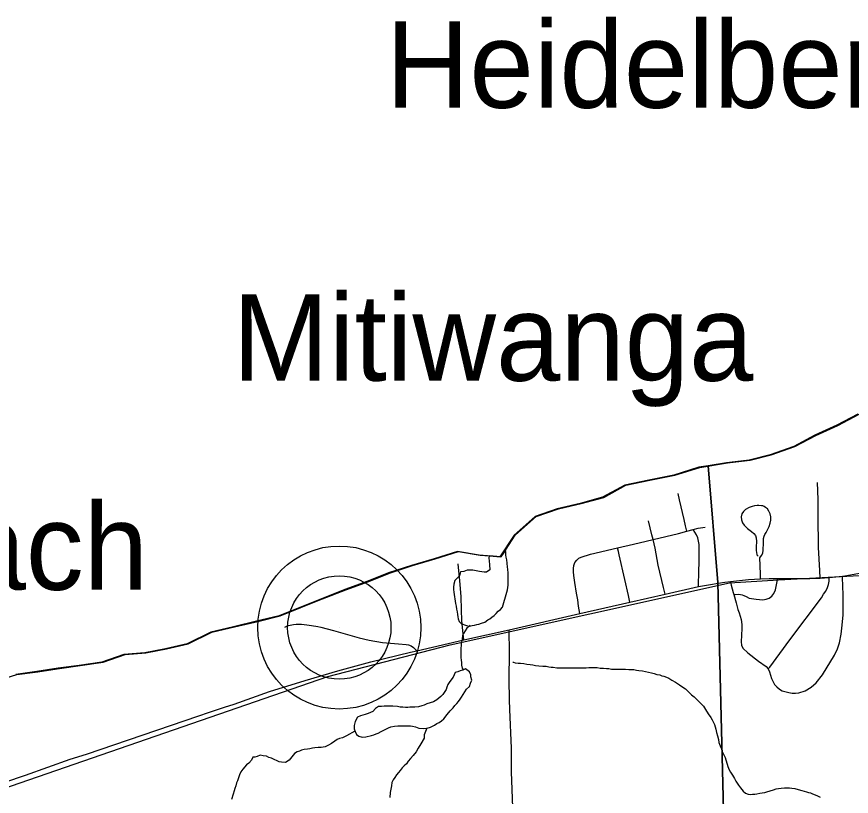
# Model space of a CAD drawing. Extents: x 0 to 34, y 0 to 22.
# Drawn here: x 7.68 to 8.441, y 18.367 to 19.079 of the extents above; entities that cross this region are included whole.
import ezdxf

# ---------------------------------------------------------------- set-up
doc = ezdxf.new("R2010")
doc.units = 0
for name, color, linetype in [('GM_X_Corporation', 7, 'Continuous'), ('GM_X_Major_Lake', 7, 'Continuous'), ('GM_X_Major_River', 7, 'Continuous'), ('GM_X_Minor_Lake', 7, 'Continuous'), ('GM_X_Minor_River', 7, 'Continuous'), ('GM_X_Rail_Line', 7, 'Continuous'), ('GM_X_Township_Road', 7, 'Continuous'), ('GM_X_Unincorporated', 7, 'Continuous'), ('GM_X_Unincorporated_Location', 7, 'Continuous'), ('GM_X_Unincorporated_Text', 7, 'Continuous'), ('GM_X_US_Route', 7, 'Continuous')]:
    doc.layers.add(name, color=color, linetype=linetype)

msp = doc.modelspace()

# ---------------------------------------------------------------- linework, layer by layer
at = {"layer": 'GM_X_Corporation'}
for points in [[(8.44753, 18.71594), (8.42818, 18.70569), (8.40806, 18.69657), (8.38909, 18.68631), (8.36745, 18.67871), (8.3481, 18.67378), (8.3276, 18.6715), (8.31086, 18.66875), (8.30218, 18.66732), (8.2794, 18.6601), (8.25663, 18.65554), (8.23461, 18.65099), (8.2145, 18.63997), (8.19401, 18.63427), (8.17313, 18.62933), (8.15302, 18.6225), (8.13366, 18.60541), (8.12075, 18.58565), (8.10178, 18.58717), (8.08205, 18.59059), (8.06079, 18.58375), (8.03992, 18.57767), (8.01905, 18.57084), (8.00007, 18.56324), (7.97919, 18.55564), (7.95794, 18.54728), (7.93821, 18.53931), (7.91923, 18.53171), (7.89873, 18.52677), (7.87748, 18.52183), (7.85699, 18.5169), (7.83535, 18.50626), (7.81562, 18.5017), (7.79664, 18.4979), (7.77766, 18.49639), (7.75755, 18.48954), (7.73668, 18.48651), (7.7177, 18.48385), (7.69796, 18.48081), (7.67899, 18.47815)], [(8.44753, 18.71594), (8.42818, 18.70569), (8.40806, 18.69657), (8.38909, 18.68631), (8.36745, 18.67871), (8.3481, 18.67378), (8.3276, 18.6715), (8.31086, 18.66875), (8.31964, 18.56207), (8.34448, 17.55856)], [(8.34448, 17.55856), (8.31964, 18.56207), (8.31086, 18.66875), (8.30218, 18.66732), (8.2794, 18.6601), (8.25663, 18.65554), (8.23461, 18.65099), (8.2145, 18.63997), (8.19401, 18.63427), (8.17313, 18.62933), (8.15302, 18.6225), (8.13366, 18.60541), (8.12075, 18.58565), (8.10178, 18.58717), (8.08205, 18.59059), (8.06079, 18.58375), (8.03992, 18.57767), (8.01905, 18.57084), (8.00007, 18.56324), (7.97919, 18.55564), (7.95794, 18.54728), (7.93821, 18.53931), (7.91923, 18.53171), (7.89873, 18.52677), (7.87748, 18.52183), (7.85699, 18.5169), (7.83535, 18.50626), (7.81562, 18.5017), (7.79664, 18.4979), (7.77766, 18.49639), (7.75755, 18.48954), (7.73668, 18.48651), (7.7177, 18.48385), (7.69796, 18.48081), (7.67899, 18.47815)]]:
    msp.add_lwpolyline(points, dxfattribs=at)
at = {"layer": 'GM_X_Major_Lake'}
for points in [[(8.12573, 18.5917), (8.13463, 18.60532), (8.15398, 18.62241), (8.1741, 18.62925), (8.19497, 18.63419), (8.21547, 18.63988), (8.23558, 18.6509), (8.2576, 18.65546), (8.28037, 18.66002), (8.30314, 18.66723), (8.32857, 18.67141), (8.34906, 18.67369), (8.36842, 18.67863), (8.39005, 18.68623), (8.40903, 18.69648), (8.42914, 18.7056), (8.4485, 18.71585)], [(7.66022, 18.47198), (7.67995, 18.47806), (7.69893, 18.48072), (7.71867, 18.48376), (7.73764, 18.48642), (7.75851, 18.48946), (7.77863, 18.4963), (7.79761, 18.49782), (7.81658, 18.50161), (7.83632, 18.50617), (7.85795, 18.51681), (7.87845, 18.52175), (7.8997, 18.52668), (7.9202, 18.53162), (7.93917, 18.53922), (7.95891, 18.5472), (7.98016, 18.55555), (8.00103, 18.56315), (8.02001, 18.57075), (8.04089, 18.57759), (8.06176, 18.58366), (8.08301, 18.5905), (8.10275, 18.58708), (8.11081, 18.58644)], [(8.11081, 18.58644), (8.11061, 18.58425), (8.11097, 18.58196), (8.11131, 18.57815), (8.11165, 18.57359), (8.10859, 18.57171), (8.10631, 18.57173), (8.10213, 18.57215), (8.09909, 18.57294), (8.09606, 18.57335), (8.0934, 18.57338), (8.09073, 18.5734), (8.08768, 18.57229), (8.08464, 18.57194), (8.08384, 18.56814), (8.07961, 18.564), (8.07882, 18.56059), (8.07841, 18.55793), (8.07839, 18.55564), (8.07874, 18.55336), (8.08016, 18.54308), (8.0809, 18.54041), (8.08125, 18.53774), (8.08161, 18.53546), (8.08196, 18.53279), (8.08232, 18.53088), (8.08268, 18.52898), (8.08342, 18.52669), (8.0853, 18.52477), (8.08833, 18.5236), (8.09022, 18.52282), (8.09288, 18.52242), (8.09555, 18.52277), (8.09745, 18.52314), (8.09974, 18.52388), (8.10164, 18.52424), (8.10393, 18.52498), (8.10699, 18.52609), (8.10967, 18.52796), (8.11158, 18.52909), (8.11349, 18.53059), (8.11541, 18.53209), (8.11733, 18.53398), (8.11925, 18.53586), (8.12117, 18.53736), (8.12309, 18.53963), (8.12703, 18.55328), (8.12781, 18.55556), (8.12824, 18.55974), (8.1283, 18.56582), (8.12835, 18.57077), (8.128, 18.57419), (8.12764, 18.5761), (8.1273, 18.57991), (8.12695, 18.58295), (8.12659, 18.58523), (8.12623, 18.58714), (8.12625, 18.58942), (8.12573, 18.5917)], [(8.11081, 18.58644), (8.12172, 18.58556), (8.12573, 18.5917)]]:
    msp.add_lwpolyline(points, dxfattribs=at)
at = {"layer": 'GM_X_Major_River'}
for points in [[(8.11081, 18.58644), (8.11061, 18.58425), (8.11097, 18.58196), (8.11131, 18.57815), (8.11165, 18.57359), (8.10859, 18.57171), (8.10631, 18.57173), (8.10213, 18.57215), (8.09909, 18.57294), (8.09606, 18.57335), (8.0934, 18.57338), (8.09073, 18.5734), (8.08768, 18.57229), (8.08464, 18.57194), (8.08384, 18.56814), (8.07961, 18.564), (8.07882, 18.56059), (8.07841, 18.55793), (8.07839, 18.55564), (8.07874, 18.55336), (8.08016, 18.54308), (8.0809, 18.54041), (8.08125, 18.53774), (8.08161, 18.53546), (8.08196, 18.53279), (8.08232, 18.53088), (8.08268, 18.52898), (8.08342, 18.52669), (8.0853, 18.52477), (8.08833, 18.5236), (8.09022, 18.52282), (8.09288, 18.52242), (8.09555, 18.52277), (8.09745, 18.52314), (8.09974, 18.52388), (8.10164, 18.52424), (8.10393, 18.52498), (8.10699, 18.52609), (8.10967, 18.52796), (8.11158, 18.52909), (8.11349, 18.53059), (8.11541, 18.53209), (8.11733, 18.53398), (8.11925, 18.53586), (8.12117, 18.53736), (8.12309, 18.53963), (8.12703, 18.55328), (8.12781, 18.55556), (8.12824, 18.55974), (8.1283, 18.56582), (8.12835, 18.57077), (8.128, 18.57419), (8.12764, 18.5761), (8.1273, 18.57991), (8.12695, 18.58295), (8.12659, 18.58523), (8.12623, 18.58714), (8.12625, 18.58942), (8.12573, 18.5917)], [(8.12573, 18.5917), (8.12172, 18.58556), (8.11081, 18.58644)]]:
    msp.add_lwpolyline(points, dxfattribs=at)
at = {"layer": 'GM_X_Minor_Lake'}
for points in [[(8.08942, 18.48326), (8.08677, 18.48216), (8.08448, 18.48142), (8.0822, 18.48068), (8.07991, 18.47994), (8.07796, 18.47578), (8.07604, 18.47313), (8.07449, 18.47087), (8.07333, 18.46897), (8.07217, 18.4667), (8.07177, 18.46442), (8.07061, 18.46253), (8.06868, 18.45989), (8.06676, 18.45801), (8.06331, 18.455), (8.06025, 18.45312), (8.0572, 18.45239), (8.05414, 18.45128), (8.05147, 18.45016), (8.04956, 18.44942), (8.04651, 18.44869), (8.04309, 18.44834), (8.04043, 18.44837), (8.03853, 18.44838), (8.03662, 18.44802), (8.03472, 18.44804), (8.03206, 18.44845), (8.02978, 18.44847), (8.02713, 18.44887), (8.02295, 18.44929), (8.02029, 18.44931), (8.01839, 18.44933), (8.01496, 18.44937), (8.01268, 18.44901), (8.01002, 18.44903), (8.00734, 18.44716), (8.00465, 18.44452), (8.00274, 18.4434), (8.00045, 18.44266), (7.99778, 18.44154), (7.99358, 18.44044), (7.99091, 18.43932), (7.98859, 18.43516), (7.98779, 18.43175), (7.98776, 18.4287), (7.98849, 18.42603)], [(8.08942, 18.48326), (8.08677, 18.48216), (8.08448, 18.48142), (8.0822, 18.48068), (8.07991, 18.47994), (8.07796, 18.47578), (8.07604, 18.47313), (8.07449, 18.47087), (8.07333, 18.46897), (8.07217, 18.4667), (8.07177, 18.46442), (8.07061, 18.46253), (8.06868, 18.45989), (8.06676, 18.45801), (8.06331, 18.455), (8.06025, 18.45312), (8.0572, 18.45239), (8.05414, 18.45128), (8.05147, 18.45016), (8.04956, 18.44942), (8.04651, 18.44869), (8.04309, 18.44834), (8.04043, 18.44837), (8.03853, 18.44838), (8.03662, 18.44802), (8.03472, 18.44804), (8.03206, 18.44845), (8.02978, 18.44847), (8.02713, 18.44887), (8.02295, 18.44929), (8.02029, 18.44931), (8.01839, 18.44933), (8.01496, 18.44937), (8.01268, 18.44901), (8.01002, 18.44903), (8.00734, 18.44716), (8.00465, 18.44452), (8.00274, 18.4434), (8.00045, 18.44266), (7.99778, 18.44154), (7.99358, 18.44044), (7.99091, 18.43932), (7.98859, 18.43516), (7.98779, 18.43175), (7.98776, 18.4287), (7.98849, 18.42603), (7.98999, 18.42336), (7.99187, 18.42182), (7.99491, 18.42103), (7.99833, 18.42138), (8.00367, 18.42247), (8.00558, 18.42321), (8.00786, 18.42395), (8.00977, 18.42469), (8.01245, 18.42619), (8.01589, 18.42806), (8.01895, 18.42955), (8.02124, 18.43029), (8.02467, 18.43102), (8.02771, 18.43137), (8.03037, 18.43135), (8.03265, 18.43132), (8.03607, 18.43129), (8.03911, 18.43126), (8.04101, 18.43086), (8.04367, 18.43046), (8.0467, 18.42929), (8.05088, 18.42887), (8.0543, 18.42922), (8.05735, 18.42995), (8.05926, 18.43107), (8.06117, 18.43182), (8.06309, 18.43332), (8.06538, 18.43444), (8.0673, 18.43594), (8.0696, 18.43782), (8.07267, 18.4416), (8.07537, 18.44499), (8.07806, 18.44763), (8.0796, 18.4499), (8.08152, 18.45178), (8.08306, 18.45367), (8.0846, 18.45556), (8.08576, 18.45745), (8.0904, 18.46463), (8.09309, 18.46727), (8.09388, 18.4703), (8.09504, 18.47295), (8.09431, 18.476), (8.09433, 18.4779), (8.09284, 18.48058), (8.08942, 18.48326)], [(7.98849, 18.42603), (7.98999, 18.42336), (7.99187, 18.42182), (7.99491, 18.42103), (7.99833, 18.42138), (8.00367, 18.42247), (8.00558, 18.42321), (8.00786, 18.42395), (8.00977, 18.42469), (8.01245, 18.42619), (8.01589, 18.42806), (8.01895, 18.42955), (8.02124, 18.43029), (8.02467, 18.43102), (8.02771, 18.43137), (8.03037, 18.43135), (8.03265, 18.43132), (8.03607, 18.43129), (8.03911, 18.43126), (8.04101, 18.43086), (8.04367, 18.43046), (8.0467, 18.42929), (8.05088, 18.42887), (8.0543, 18.42922), (8.05735, 18.42995), (8.05926, 18.43107), (8.06117, 18.43182), (8.06309, 18.43332), (8.06538, 18.43444), (8.0673, 18.43594), (8.0696, 18.43782), (8.07267, 18.4416), (8.07537, 18.44499), (8.07806, 18.44763), (8.0796, 18.4499), (8.08152, 18.45178), (8.08306, 18.45367), (8.0846, 18.45556), (8.08576, 18.45745), (8.0904, 18.46463), (8.09309, 18.46727), (8.09388, 18.4703), (8.09504, 18.47295), (8.09431, 18.476), (8.09433, 18.4779), (8.09284, 18.48058), (8.08942, 18.48326)]]:
    msp.add_lwpolyline(points, dxfattribs=at)
at = {"layer": 'GM_X_Minor_River'}
for points in [[(8.09364, 18.52279), (8.09058, 18.52054), (8.08749, 18.51562), (8.08671, 18.51373), (8.0863, 18.51031), (8.0855, 18.50689), (8.08548, 18.50499), (8.08507, 18.50195), (8.08505, 18.50005), (8.08503, 18.49815), (8.08499, 18.49359), (8.08535, 18.4913), (8.0857, 18.48902), (8.08568, 18.48673), (8.08641, 18.48406), (8.08719, 18.48233)], [(8.13247, 18.48934), (8.13323, 18.48933), (8.13475, 18.48893), (8.1374, 18.48853), (8.13968, 18.48851), (8.14272, 18.4881), (8.14538, 18.48769), (8.14842, 18.48728), (8.15069, 18.48688), (8.15335, 18.48648), (8.15639, 18.48607), (8.15981, 18.48565), (8.16285, 18.48563), (8.1655, 18.48522), (8.1674, 18.48482), (8.1693, 18.48481), (8.17272, 18.48439), (8.17462, 18.48438), (8.1769, 18.48435), (8.1788, 18.48434), (8.18071, 18.48432), (8.1826, 18.4843), (8.18451, 18.48428), (8.18679, 18.48426), (8.19477, 18.48418), (8.19705, 18.48416), (8.19933, 18.48414), (8.202, 18.4845), (8.20466, 18.48447), (8.20694, 18.48445), (8.2096, 18.48442), (8.21226, 18.48402), (8.2153, 18.48399), (8.21796, 18.48359), (8.22024, 18.48356), (8.22251, 18.48316), (8.22442, 18.48314), (8.2267, 18.48312), (8.2286, 18.4831), (8.2305, 18.48309), (8.23316, 18.48306), (8.23544, 18.48304), (8.23848, 18.48263), (8.24038, 18.48261), (8.24304, 18.48259), (8.24532, 18.48219), (8.24759, 18.48179), (8.25101, 18.48137), (8.25367, 18.48097), (8.25632, 18.48018), (8.25898, 18.47977), (8.26163, 18.47899), (8.26391, 18.47821), (8.26656, 18.4778), (8.26846, 18.47702), (8.27035, 18.47663), (8.27263, 18.47584), (8.2749, 18.47468), (8.27754, 18.47313), (8.28095, 18.4712), (8.28472, 18.46888), (8.28774, 18.46657), (8.29001, 18.46503), (8.29566, 18.45965), (8.29792, 18.45773), (8.2998, 18.45581), (8.30168, 18.45427), (8.30357, 18.45235), (8.30658, 18.44928), (8.30845, 18.44622), (8.31069, 18.4424), (8.31332, 18.43895), (8.31443, 18.43666), (8.31555, 18.43436), (8.31667, 18.43245), (8.31777, 18.42826), (8.3185, 18.42521), (8.31923, 18.42216), (8.32034, 18.41872), (8.32069, 18.41606), (8.3218, 18.41301), (8.32291, 18.41033), (8.32365, 18.40766), (8.32477, 18.40537), (8.32625, 18.40231), (8.32699, 18.40041), (8.3281, 18.39621), (8.32884, 18.3943), (8.32995, 18.39125), (8.33106, 18.38896), (8.33294, 18.38628), (8.33481, 18.38322), (8.33592, 18.38092), (8.33742, 18.37901), (8.33855, 18.37709), (8.34042, 18.3748), (8.34267, 18.37173), (8.34494, 18.36981), (8.34721, 18.36903), (8.34949, 18.36863), (8.35139, 18.36899)], [(7.98835, 18.42655), (7.98085, 18.4223), (7.97703, 18.42044), (7.97436, 18.4197), (7.97208, 18.41896), (7.97016, 18.41746), (7.96709, 18.41521), (7.96442, 18.41371), (7.96136, 18.41222), (7.95755, 18.41149), (7.95489, 18.41152), (7.95185, 18.41116), (7.94956, 18.41081), (7.94728, 18.41045), (7.94499, 18.41009), (7.94195, 18.40974), (7.93966, 18.409), (7.93775, 18.40826), (7.93584, 18.40751), (7.93316, 18.40602), (7.92854, 18.39998), (7.9251, 18.39773), (7.9213, 18.39814), (7.9194, 18.39854), (7.91751, 18.39932), (7.91486, 18.40048), (7.91221, 18.40165), (7.90994, 18.40243), (7.90767, 18.40359), (7.90463, 18.404), (7.90197, 18.40441), (7.8993, 18.40329), (7.89701, 18.40256), (7.89511, 18.40257), (7.89394, 18.39992), (7.89163, 18.39728), (7.88934, 18.39578), (7.88625, 18.39163), (7.88433, 18.38936), (7.88316, 18.38671), (7.88121, 18.38102), (7.88042, 18.37913), (7.87964, 18.37648), (7.87885, 18.3742), (7.87807, 18.37193), (7.87728, 18.36889), (7.87571, 18.36396)], [(8.05406, 18.42919), (8.05158, 18.42316), (8.05155, 18.42012), (8.04845, 18.41482), (8.04613, 18.41104), (8.0442, 18.40763), (8.0415, 18.40424), (8.0392, 18.40159), (8.03689, 18.39895), (8.03535, 18.39669), (8.03342, 18.39481), (8.0315, 18.39292), (8.02958, 18.39066), (8.02804, 18.38877), (8.0265, 18.3865), (8.02495, 18.38423), (8.02341, 18.38197), (8.02225, 18.3797), (8.02184, 18.37666), (8.02104, 18.37362), (8.02063, 18.37058), (8.02021, 18.36602)], [(8.35139, 18.36899), (8.35329, 18.36897), (8.3552, 18.36933), (8.35786, 18.36969), (8.36015, 18.37005), (8.36243, 18.37041), (8.36434, 18.37115), (8.36739, 18.37188), (8.37044, 18.37299), (8.37273, 18.37373), (8.37502, 18.37409), (8.3773, 18.37445), (8.38035, 18.3748), (8.38263, 18.37478), (8.38491, 18.37476), (8.38718, 18.37436), (8.38984, 18.37395), (8.39288, 18.37316), (8.39629, 18.37237), (8.39856, 18.37159), (8.40046, 18.37119), (8.40235, 18.37041), (8.40425, 18.37001), (8.40614, 18.36923), (8.40842, 18.36845), (8.41069, 18.36729), (8.41296, 18.36613)]]:
    msp.add_lwpolyline(points, dxfattribs=at)
at = {"layer": 'GM_X_Rail_Line'}
msp.add_lwpolyline([(6.87885, 18.29227), (7.10148, 18.25871), (7.18271, 18.24997), (7.28141, 18.25347), (7.4098, 18.28492), (7.96356, 18.47627), (8.07536, 18.5051), (8.3304, 18.56189), (8.37494, 18.56451), (8.45443, 18.56888), (8.5243, 18.58723), (8.9, 18.69387)], dxfattribs=at)
at = {"layer": 'GM_X_Township_Road'}
msp.add_line((8.29147, 18.60904), (8.29716, 18.61054), dxfattribs=at)
for points in [[(8.41302, 18.56615), (8.41265, 18.57309), (8.41152, 18.594), (8.41105, 18.62299), (8.41107, 18.63801), (8.41048, 18.65345)], [(8.29147, 18.60904), (8.29011, 18.61395), (8.28877, 18.61954), (8.28458, 18.63768), (8.28342, 18.64341)], [(8.35781, 18.58474), (8.3594, 18.58673), (8.36061, 18.58884), (8.36104, 18.59162), (8.3613, 18.59824), (8.36143, 18.60232), (8.36191, 18.60459), (8.3625, 18.60603), (8.36369, 18.60784), (8.36475, 18.60954), (8.36638, 18.61338), (8.36736, 18.61618), (8.36792, 18.61906), (8.36797, 18.62197), (8.36745, 18.62479), (8.36626, 18.62733), (8.3649, 18.62938), (8.36309, 18.63077), (8.36189, 18.63158), (8.36061, 18.63201), (8.35933, 18.63228), (8.3569, 18.6323), (8.35564, 18.6323), (8.35298, 18.63201), (8.35097, 18.63158), (8.34811, 18.63063), (8.3449, 18.6289), (8.34292, 18.62703), (8.34167, 18.62492), (8.34104, 18.62202), (8.34133, 18.61929), (8.34217, 18.61653), (8.34355, 18.61452), (8.34684, 18.61134), (8.35023, 18.6088), (8.35244, 18.60699), (8.354, 18.60519), (8.35464, 18.60289), (8.35492, 18.59972), (8.35475, 18.5947), (8.35457, 18.59237), (8.35457, 18.59099), (8.3548, 18.58972), (8.35536, 18.58745), (8.35633, 18.58627)], [(8.26059, 18.6013), (8.25936, 18.60562), (8.25624, 18.61852)], [(8.26059, 18.6013), (8.28379, 18.60689), (8.29147, 18.60904)], [(8.29716, 18.61054), (8.30176, 18.61161), (8.30793, 18.61256)], [(8.30194, 18.55852), (8.30203, 18.56246), (8.30219, 18.56904), (8.30219, 18.5719), (8.30263, 18.58134), (8.3027, 18.59074), (8.30273, 18.59381), (8.30253, 18.59685), (8.30207, 18.59984), (8.30127, 18.60279), (8.30009, 18.60564), (8.29876, 18.60825), (8.29716, 18.61054)], [(8.22796, 18.59378), (8.24273, 18.59728), (8.25427, 18.59977), (8.26059, 18.6013)], [(8.27155, 18.5516), (8.27013, 18.55763), (8.2653, 18.57805), (8.26231, 18.59335), (8.26059, 18.6013)], [(8.19274, 18.58445), (8.19481, 18.58533), (8.20328, 18.58792), (8.22796, 18.59378)], [(8.23941, 18.54425), (8.23807, 18.55038), (8.23489, 18.5649), (8.2296, 18.58728), (8.22883, 18.59033), (8.22796, 18.59378)], [(8.08774, 18.50968), (8.08693, 18.51818), (8.08604, 18.52754), (8.08559, 18.53705), (8.08523, 18.54946), (8.08422, 18.5636), (8.08277, 18.57907)], [(8.1936, 18.53378), (8.19261, 18.5405), (8.19173, 18.54642), (8.19066, 18.55244), (8.18913, 18.5621), (8.18815, 18.56863), (8.18792, 18.57178), (8.18796, 18.5748), (8.18835, 18.57765), (8.18912, 18.58031), (8.19107, 18.58266), (8.19274, 18.58445)], [(8.35867, 18.56536), (8.3585, 18.56956), (8.35817, 18.5777), (8.35781, 18.58474)], [(8.33112, 18.56308), (8.33194, 18.55978), (8.33361, 18.55305), (8.33412, 18.55121)], [(8.33412, 18.55121), (8.33552, 18.55134), (8.3388, 18.55164), (8.34169, 18.55076), (8.34322, 18.55038), (8.34556, 18.54947), (8.34835, 18.54798), (8.35452, 18.54679), (8.36084, 18.54648), (8.36376, 18.54682), (8.36655, 18.5477), (8.36903, 18.5496), (8.37074, 18.55223), (8.37222, 18.5556), (8.37366, 18.56302), (8.37419, 18.56572)], [(8.3655, 18.48332), (8.36676, 18.48051), (8.36851, 18.47459), (8.37134, 18.46912), (8.37336, 18.46679), (8.37576, 18.46485), (8.37845, 18.46333), (8.38436, 18.46159), (8.38741, 18.46118), (8.39049, 18.46114), (8.39355, 18.46151), (8.39941, 18.46341), (8.40471, 18.46655), (8.40927, 18.47069), (8.41502, 18.47794), (8.42603, 18.49586), (8.42888, 18.50171), (8.43055, 18.50707), (8.43214, 18.51494), (8.43323, 18.52329), (8.43407, 18.53249), (8.43404, 18.552), (8.43384, 18.55767), (8.43347, 18.56794)], [(8.3655, 18.48332), (8.36715, 18.48491), (8.38523, 18.50969), (8.41416, 18.54821), (8.41621, 18.55136), (8.41807, 18.55423), (8.41966, 18.55767), (8.42048, 18.56018), (8.42092, 18.56171), (8.4212, 18.56325), (8.42135, 18.56662)], [(8.33412, 18.55121), (8.33626, 18.54349), (8.33797, 18.53749), (8.33923, 18.53451), (8.34088, 18.52848), (8.34139, 18.52379), (8.34151, 18.52014), (8.34105, 18.50786), (8.3412, 18.50483), (8.34257, 18.50218), (8.34701, 18.49799), (8.35663, 18.49033), (8.36364, 18.48542), (8.3655, 18.48332)], [(7.92434, 18.52125), (7.92794, 18.5228), (7.93248, 18.52391), (7.9348, 18.52409), (7.93971, 18.5241), (7.94453, 18.52364), (7.94868, 18.52278), (7.95452, 18.52195), (7.95744, 18.52129), (7.96897, 18.51837), (7.99242, 18.51155), (8.00142, 18.50938), (8.0135, 18.50738), (8.02834, 18.50618), (8.03516, 18.50546), (8.03723, 18.5053), (8.03973, 18.50419), (8.04195, 18.5028), (8.04362, 18.50114), (8.04491, 18.49983)], [(8.15168, 17.74779), (8.15142, 17.75677), (8.14975, 17.80021), (8.14798, 17.86541), (8.14653, 17.92128), (8.14453, 17.9894), (8.14401, 18.02038), (8.14249, 18.07619), (8.14222, 18.09163), (8.13989, 18.18468), (8.13806, 18.21881), (8.1352, 18.29323), (8.13418, 18.31491), (8.13293, 18.34888), (8.13133, 18.38922), (8.13139, 18.41084), (8.12992, 18.44609), (8.1294, 18.45498), (8.1291, 18.47351), (8.12958, 18.4983), (8.12914, 18.51904)]]:
    msp.add_lwpolyline(points, dxfattribs=at)
at = {"layer": 'GM_X_Unincorporated'}
for radius in [0.0744, 0.04716]:
    msp.add_circle((7.97416, 18.52107), radius, dxfattribs=at)
at = {"layer": 'GM_X_Unincorporated_Location'}
msp.add_line((7.97416, 18.52107), (7.97416, 18.52107), dxfattribs=at)
at = {"layer": 'GM_X_US_Route'}
msp.add_line((8.31289, 18.56035), (8.31986, 18.56152), dxfattribs=at)
for points in [[(8.31986, 18.56152), (8.32605, 18.56255), (8.33112, 18.56308), (8.34775, 18.56484), (8.35867, 18.56536), (8.36643, 18.56573), (8.37419, 18.56572), (8.40358, 18.56567), (8.41302, 18.56615), (8.42135, 18.56662), (8.43347, 18.56794), (8.43749, 18.5684), (8.45572, 18.57187), (8.45694, 18.57219), (8.49183, 18.58102), (8.54269, 18.59531), (8.56194, 18.60079), (8.62933, 18.61997), (8.68909, 18.63711), (8.70943, 18.64282), (8.79382, 18.66651), (8.84201, 18.68017), (8.9, 18.69661)], [(7.63175, 18.36742), (7.68764, 18.38635), (7.72866, 18.40082), (7.74338, 18.40559), (7.84593, 18.44035), (7.85465, 18.44345), (7.86933, 18.44835), (7.87823, 18.4512), (7.91049, 18.4625), (7.94306, 18.47281), (7.97284, 18.48157), (8.0028, 18.48966), (8.03899, 18.49847), (8.04491, 18.49983), (8.08774, 18.50968), (8.12914, 18.51904), (8.1936, 18.53378), (8.23941, 18.54425), (8.27155, 18.5516), (8.30194, 18.55852), (8.31289, 18.56035)]]:
    msp.add_lwpolyline(points, dxfattribs=at)

# ---------------------------------------------------------------- texts
at = {"layer": 'GM_X_Unincorporated_Text'}
for s, height, p in [('Heidelberg Beach', 0.0789773, (8.01667, 18.99548)), ('Mitiwanga', 0.078977, (7.87667, 18.74632)), ('Ruggles Beach', 0.0789773, (7.08334, 18.55548))]:
    msp.add_text(s, height=height, rotation=0.00001, dxfattribs=at).set_placement(p)

doc.saveas('drawing.dxf')
